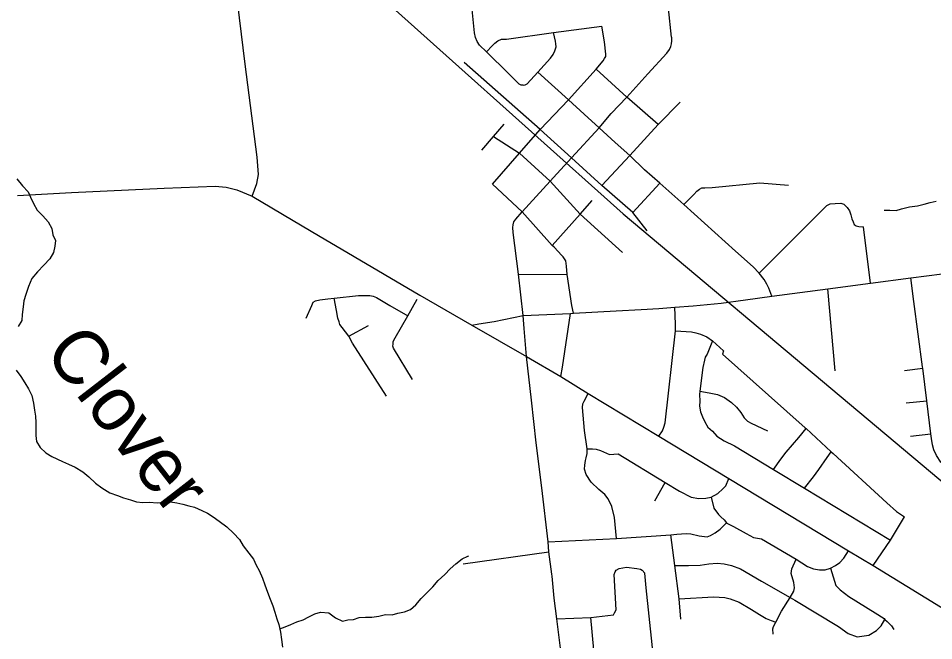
# Model space of a CAD drawing. Extents: x 114843 to 284848, y 317643 to 566895.
# Drawn here: x 156246 to 164672, y 408606 to 414334 of the extents above; entities that cross this region are included whole.
import ezdxf

# ---------------------------------------------------------------- set-up
doc = ezdxf.new("R2010")
doc.units = 0
for name, color, linetype in [('GM_X_City_Street', 7, 'Continuous'), ('GM_X_County_Road', 7, 'Continuous'), ('GM_X_Minor_River', 7, 'Continuous'), ('GM_X_Minor_River_Text', 7, 'Continuous'), ('GM_X_Rail_Line', 7, 'Continuous')]:
    doc.layers.add(name, color=color, linetype=linetype)

msp = doc.modelspace()

# ---------------------------------------------------------------- linework, layer by layer
at = {"layer": 'GM_X_City_Street'}
for p, q in [((161902.9, 412546.1), (162152.3, 412817.2)), ((164090.6, 411896.7), (164027.6, 412413.6)), ((160849.1, 411978.3), (161299.5, 411975.8)), ((163766.8, 411091.1), (163696.7, 411845.5)), ((159289.1, 411407.6), (159470.8, 411506)), ((164402.7, 411093.2), (164572.3, 411113.7)), ((164419.5, 410796.3), (164609.3, 410813.9)), ((164460.3, 410489.5), (164646.9, 410510)), ((162104.6, 409891.9), (162200.3, 410061)), ((160342.6, 409314.4), (161129.8, 409424))]:
    msp.add_line(p, q, dxfattribs=at)
for points in [[(160893, 413717.5), (160875.8, 413718.9), (160857.8, 413728.2), (160759.5, 413826.6), (160555.2, 414024.2), (160492.3, 414087.7), (160470.2, 414120.4), (160455.9, 414157.7), (160446.2, 414199.8), (160424.3, 414415.1)], [(160555.2, 414024.2), (160607.8, 414080.8), (160632.6, 414105.9), (160659, 414128), (160693.3, 414140.7), (160739.1, 414143.1), (161173.5, 414202.2), (161617.6, 414262.7)], [(160612, 412807.9), (160860.1, 413094.1), (161048.9, 413311.2), (161311.6, 413583.1), (161565.6, 413865.2), (161629.8, 413943.7), (161641.3, 413963.3), (161653.7, 413981.3), (161655.1, 414004.8), (161641.8, 414118.6), (161617.6, 414262.7)], [(160893, 413717.5), (160912.5, 413720.8), (160931.2, 413731.1), (161027.2, 413839.5), (161144.1, 413968.3), (161168.1, 414000.5), (161185.8, 414034.2), (161196.4, 414070.9), (161195.5, 414098.3), (161191.4, 414124.8), (161173.5, 414202.2)], [(162034, 412377.6), (161902.9, 412546.1), (161618.5, 412793.9), (161337.8, 413050.3), (161048.9, 413311.2), (160349.6, 413928.6)], [(161592.8, 413325.1), (161454.6, 413453), (161311.6, 413583.1), (161027.2, 413839.5)], [(162135.9, 413356.5), (161847.8, 413609.9), (161565.6, 413865.2)], [(161618.5, 412793.9), (161874.1, 413072), (162135.9, 413356.5), (162338.9, 413562.4)], [(160512.9, 413120.2), (160621.5, 413246.3), (160718.4, 413358.8)], [(163181.5, 411775.6), (163154.4, 411849.5), (163135.4, 411887.6), (163110.9, 411931.2), (163066, 411989.4), (163010.2, 412046), (162848.3, 412190), (162372.2, 412619), (162152.3, 412817.2), (162010.9, 412941.1), (161874.1, 413072), (161739.5, 413189.7), (161592.8, 413325.1)], [(160621.5, 413246.3), (160860.1, 413094.1), (161141.1, 412834.6), (161416.6, 412530.9), (161807, 412179.7)], [(161275.2, 412119.4), (161263, 412137.4), (161246.9, 412155.2), (161216.6, 412187), (161178.3, 412226.7), (161161.8, 412242.1), (160884.6, 412552.9), (160612, 412807.9)], [(162372.2, 412619), (162462.9, 412712.5), (162491.6, 412742.4), (162517.2, 412762.1), (162539, 412772.4), (162566.3, 412774.9), (162632.6, 412778.5), (163073.3, 412819.2), (163336.8, 412797.6)], [(161161.8, 412242.1), (161416.6, 412530.9), (161528, 412657.2)], [(163066, 411989.4), (163690.1, 412612.7), (163718, 412627), (163765.9, 412629.5), (163817.8, 412632), (163845.9, 412622.3), (163876.1, 412592.5), (163896.3, 412562.6), (163910.7, 412524.7), (163919, 412488.7), (163931.2, 412460.7), (163939.4, 412436.8), (163957.6, 412422.9), (163983.6, 412419.2), (164027.6, 412413.6)], [(161356.5, 411619), (161340.3, 411690), (161299.5, 411975.8), (161291.8, 412053.4), (161287.3, 412101.5), (161275.2, 412119.4)], [(165070.1, 409807.3), (165054, 409829.3), (165019.7, 409941.6), (165007.7, 409971.6), (164983.6, 410005.7), (164853.2, 410143.6), (164813.6, 410179.8), (164736.9, 410249.6), (164696.8, 410309.7), (164672.6, 410361.7), (164662.5, 410409.9), (164652.4, 410466), (164646.9, 410510), (164609.3, 410813.9), (164572.3, 411113.7), (164570.5, 411127.8), (164488.9, 411727.4), (164461.9, 411944.2)], [(158896.7, 411574.5), (158947.6, 411691.3), (158961.3, 411721.5), (158983.2, 411733.7), (159023.1, 411742.1), (159094.9, 411750.9), (159154.8, 411757.4), (159378.3, 411781.8), (159444.2, 411784.4), (159482.2, 411782.8), (159512.2, 411777.1), (159542.3, 411763.3), (159664.8, 411692.4), (159832.1, 411596.3)], [(159636.5, 410856.1), (159322.4, 411344.2), (159289.1, 411407.6), (159227.2, 411487.6), (159207, 411515.4), (159200.7, 411539.4), (159188.4, 411573.4), (159175.8, 411645.4), (159154.8, 411757.4)], [(159874.8, 411010.9), (159700.4, 411297.8), (159694.3, 411315.8), (159698.1, 411335.9), (159697.8, 411359.9), (159715.5, 411392.2), (159832.1, 411596.3), (159918.7, 411748.1)], [(162141.5, 410489.6), (162175.2, 410538.3), (162189.4, 410570.4), (162201.5, 410611.7), (162294.7, 411458), (162295.5, 411519.2), (162290.3, 411674.1)], [(161239.3, 411038), (161256.2, 411124.7), (161329.7, 411617.1)], [(162294.7, 411458), (162443.9, 411447.5), (162481.8, 411440.1), (162524.4, 411427.7), (162582.9, 411401.3), (162636.7, 411365), (162736.4, 411274.3), (162729.7, 411241.9), (163150.7, 410867.1), (163489.1, 410565.8), (163497.3, 410558.3), (163729.2, 410344.3), (163747, 410327.9), (164240, 409876.2), (164329.3, 409794.4), (164403.7, 409745.1)], [(162636.7, 411365), (162585.9, 411242.4), (162570.1, 411216.2), (162562.4, 411188.1), (162547, 411119.7), (162519.3, 410901.7), (162515.3, 410870.8), (162519.9, 410810.8), (162516.3, 410764.6), (162526.8, 410712.6), (162543.2, 410666.6), (162565.6, 410620.7), (162594, 410570.9), (162636.3, 410533.3), (162676.7, 410489.5), (162745, 410446.1), (162837.3, 410398.9), (163197.7, 410181.6), (163483.4, 410009.2), (164275.4, 409531.5)], [(161751.9, 409546), (161735.1, 409740.2), (161710.8, 409842.5), (161674.6, 409912.6), (161644.5, 409952.6), (161588.4, 409996.6), (161518.2, 410064.6), (161474, 410136.6), (161457.9, 410184.8), (161459.8, 410220.9), (161468.3, 410262.9), (161473.6, 410289.1), (161483.5, 410327.3), (161481.4, 410371.4), (161456.9, 410541.9), (161439.3, 410751.7), (161442.2, 410786.8), (161453.4, 410811.6), (161493.1, 410882)], [(162519.3, 410901.7), (162607.1, 410885.8), (162681.1, 410872.5), (162747.3, 410843.1), (162809.7, 410797.6), (162858, 410756), (162896.4, 410706.2), (162928.9, 410656.5), (162957.1, 410626.7), (162993.2, 410607), (163141.7, 410536.3)], [(163197.7, 410181.6), (163264, 410276.9), (163315.3, 410341.6), (163430, 410475), (163497.3, 410558.3)], [(161481.4, 410371.4), (161531.4, 410371.6), (161565.4, 410369.7), (161605.4, 410357.8), (161687.5, 410319.9), (161769.4, 410327.1), (162200.3, 410061), (162332.9, 409983.5), (162438.5, 409927.6), (162509.8, 409913.6), (162573.7, 409916.2), (162624.2, 409925.8), (162685.8, 409960.3), (162731.9, 410002.9), (162758.5, 410029.9), (162787.9, 410098.2)], [(163483.4, 410009.2), (163565.2, 410113.5), (163614.5, 410180.2), (163691.4, 410291.2), (163729.2, 410344.3)], [(162624.2, 409925.8), (162648.6, 409825.5), (162692.8, 409767.4), (162714.2, 409746), (162742.9, 409717.4), (162766, 409690.9), (162769, 409687.4), (162829, 409655.5), (162947.2, 409591.7), (163013.3, 409555.8), (163087.9, 409542.4), (163404.9, 409355.9), (163511.6, 409287.6), (163566.4, 409266.3), (163620.1, 409257.4), (163672.7, 409258.8), (163722.1, 409272.6), (163769.4, 409296.7), (163809.4, 409326.9), (163846.3, 409365.3), (163888, 409432.6)], [(161122.3, 409515.5), (161751.9, 409546), (162252.7, 409581.7), (162307.4, 409585.6), (162393.3, 409591.9), (162437.3, 409590.1), (162513.4, 409570.2), (162587.3, 409562.5), (162619.3, 409572.6), (162661.2, 409598.8), (162707.1, 409631.1), (162766, 409690.9)], [(164113.8, 409299.2), (164275.4, 409531.5), (164403.7, 409745.1)], [(162345.5, 408803.3), (162329.2, 408991.8), (162289.7, 409296.6), (162252.7, 409581.7)], [(163193.7, 408665.6), (163191.6, 408713.7), (163197.5, 408735.8), (163218.3, 408775.7), (163271.1, 408876.5), (163350.9, 409003.4), (163384.6, 409061.5), (163392.4, 409093.6), (163384.3, 409141.7), (163360.1, 409223.9), (163368, 409266.1), (163404.9, 409355.9)], [(161202.8, 408808.4), (161515.7, 408818.6), (161723.6, 408843.4), (161735.5, 408861.5), (161749.4, 408889.6), (161730.5, 409214.6), (161740.5, 409238.7), (161750.4, 409254.8), (161778.4, 409268.9), (161844.3, 409283.2), (161940.3, 409271.4), (161972.3, 409263.5), (161988.4, 409255.5)], [(162289.7, 409296.6), (162416.1, 409299.1), (162524.1, 409301.4), (162604, 409313.7), (162678, 409320), (162744, 409314.2), (162812, 409298.4), (162894.1, 409266.5), (163088.4, 409154.8), (163350.9, 409003.4), (163392.8, 408979.2), (163795.4, 408737.8), (163885.5, 408671.9), (163967.6, 408642.1), (164075.5, 408656.5), (164145.4, 408698.8), (164189.2, 408743.1), (164223.1, 408801.8)], [(163722.1, 409272.6), (163770.3, 409114.9), (163812.4, 409072.9), (163890.6, 409013), (164134.9, 408861.3), (164215.1, 408809.4), (164223.1, 408801.8), (164245.1, 408781.4), (164285.2, 408741.4), (164305.3, 408707.4)], [(162108.7, 408278.6), (162079.4, 408569.8), (162026.8, 409093.2), (162012.4, 409227.5), (161988.4, 409255.5)], [(162329.2, 408991.8), (162646.9, 409010.9), (162750.9, 409003.2), (162798.9, 408991.3), (162883, 408959.5), (162995.1, 408891.7), (163069.2, 408845.8), (163131.3, 408809.9), (163177.3, 408792), (163218.3, 408775.7)], [(161591.2, 408275.2), (161577.2, 408283.2), (161565.1, 408309.2), (161560.9, 408357.3), (161544.8, 408521.6), (161515.7, 408818.6)]]:
    msp.add_lwpolyline(points, dxfattribs=at)
at = {"layer": 'GM_X_County_Road'}
for p, q in [((158398.4, 412697.1), (158858.1, 412424.8)), ((160420.1, 411510.6), (160925.4, 411220.8)), ((160925.4, 411220.8), (161239.3, 411038))]:
    msp.add_line(p, q, dxfattribs=at)
for points in [[(158398.4, 412697.1), (158442, 412813.2), (158458.3, 412898.1), (158445.4, 413055.7), (158334.3, 413911.3), (158213.9, 414893.5), (158105, 415909.2), (158076.9, 416138.5)], [(162260.6, 414156.4), (162260.2, 414162), (162232.1, 414424.7), (162211.2, 414612.4), (162205.7, 414660.4)], [(161592.8, 413325.1), (161704.8, 413457.1), (161847.8, 413609.9), (162040, 413821.8), (162214.8, 414013.7), (162238.9, 414047.4), (162254, 414075), (162259.9, 414099.4), (162262.8, 414128.4), (162260.6, 414156.4)], [(161173.9, 412870.5), (161337.8, 413050.3), (161592.8, 413325.1)], [(160802.1, 412361.6), (160797.9, 412408.9), (160800, 412434.8), (160806.7, 412461.6), (160826.4, 412486.1), (160884.6, 412552.9), (161141.1, 412834.6), (161173.9, 412870.5)], [(156237.8, 412704.3), (156734.6, 412729.8), (157588.4, 412772), (158058.2, 412789.6), (158160.1, 412780.7), (158256.3, 412756.4), (158398.4, 412697.1)], [(163181.5, 411775.6), (163696.7, 411845.5), (164090.6, 411896.7), (164461.9, 411944.2), (164748.9, 411982.3), (165028, 412018.7), (165821.1, 412121.1), (166821.7, 412255.2), (168352.4, 412416.6), (169278.9, 412517.6), (169332.7, 412524.4)], [(158858.1, 412424.8), (159009.8, 412335), (159943.7, 411784.7), (160420.1, 411510.6)], [(160925.4, 411220.8), (160903.7, 411480.7), (160893.6, 411598.2), (160849.1, 411978.3), (160802.1, 412361.6)], [(161979.5, 411655.1), (162142.4, 411664.3), (162290.3, 411674.1), (162459.7, 411687.5), (162714.6, 411712), (162938.6, 411741.6), (163181.5, 411775.6)], [(160893.6, 411598.2), (161329.7, 411617.1), (161356.5, 411619), (161748.3, 411642.2), (161979.5, 411655.1)], [(160420.1, 411510.6), (160484.2, 411521.3), (160625.6, 411542.7), (160893.6, 411598.2)], [(161156.2, 409219), (161129.8, 409424), (161122.3, 409515.5), (161063.8, 410013.8), (161014.3, 410427.6), (160969.5, 410820), (160925.4, 411220.8)], [(161239.3, 411038), (161493.1, 410882), (162141.5, 410489.6), (162787.9, 410098.2), (163888, 409432.6), (164113.8, 409299.2), (164910.5, 408810.9), (165505.1, 408443.8), (166074.9, 408100.4), (166322.4, 407953.6), (166384.6, 407921.1), (166715.7, 407773.9), (166942.2, 407679.6), (167338.4, 407508.2), (167631.2, 407392.7), (167756, 407349.7)], [(161486.7, 407363.3), (161447.7, 407428.2), (161406.9, 407527.7), (161389.9, 407571.4), (161375.1, 407612.9), (161357.9, 407670.4), (161343.6, 407699), (161332.4, 407758.4), (161264.4, 408316.1), (161202.8, 408808.4), (161179.4, 408997.3), (161158.9, 409198.5), (161156.2, 409219)]]:
    msp.add_lwpolyline(points, dxfattribs=at)
at = {"layer": 'GM_X_Minor_River'}
for points in [[(156232.5, 412857.7), (156284.1, 412791.2), (156337.8, 412736.8), (156357.5, 412686.5)], [(156357.5, 412686.5), (156387.2, 412630.2), (156418.8, 412569.8), (156470.5, 412515.4), (156520.2, 412460.9), (156553.8, 412400.5), (156563.5, 412340.3), (156589.2, 412290), (156580.9, 412235.9), (156570.6, 412179.9), (156536.2, 412119.9), (156479.9, 412062.1), (156423.5, 412002.3), (156369.2, 411938.5), (156340.7, 411866.5), (156316.3, 411792.4), (156298, 411732.4), (156291.7, 411678.3), (156281.3, 411608.2), (156279, 411554), (156244.6, 411498.1)], [(164215.6, 412568.6), (164269.6, 412568.3), (164325.5, 412564), (164375.6, 412579.7), (164449.8, 412599.3), (164521.8, 412608.9), (164583.9, 412622.6), (164640, 412638.3), (164694.1, 412650)], [(156226.3, 411095.2), (156270, 411038.7), (156307.6, 410980.4), (156341.3, 410924), (156369, 410861.7), (156384.6, 410791.4), (156396.2, 410727.2), (156403.9, 410673), (156407.5, 410612.8), (156406.9, 410494.5), (156414.5, 410440.3), (156446.2, 410384), (156499.9, 410333.5), (156555.8, 410301.1), (156653.5, 410254.3), (156709.4, 410231.9), (156769.2, 410203.5), (156841, 410161), (156894.7, 410112.5), (156956.4, 410056), (157014.1, 410013.5), (157087.9, 409966.9), (157159.7, 409942.4), (157213.6, 409920), (157279.5, 409901.6), (157335.4, 409885.2), (157393.4, 409878.8), (157453.4, 409880.5), (157525.4, 409876), (157597.4, 409879.6), (157647.4, 409883.3), (157705.4, 409874.9), (157761.3, 409862.5), (157815.2, 409848.2), (157869.2, 409835.8), (157935, 409805.3), (157986.8, 409778.9), (158038.6, 409744.5), (158096.4, 409706.1), (158164.1, 409653.5), (158227.8, 409595), (158281.5, 409538.5), (158317.2, 409480.2), (158366.8, 409411.7), (158410.5, 409357.3), (158436.1, 409301), (158463.9, 409250.7), (158493.5, 409182.3), (158515.1, 409120), (158540.7, 409053.7), (158564.4, 408989.4), (158588, 408927.1), (158607.7, 408868.8), (158627.3, 408808.5), (158643, 408754.3), (158660.6, 408684), (158670.2, 408617.8), (158677.8, 408547.6)], [(158653, 408714.6), (158702.9, 408733.9), (158755, 408755.6), (158811.2, 408779.4), (158867.3, 408799.1), (158921.5, 408826.8), (158975.6, 408852.5), (159027.7, 408868.3), (159103.7, 408863.8), (159165.4, 408815.3), (159229.3, 408786.8), (159279.3, 408798.6), (159331.4, 408802.3), (159383.5, 408820), (159443.5, 408823.6), (159501.5, 408823.3), (159565.6, 408832.9), (159625.6, 408846.6), (159687.6, 408844.2), (159739.7, 408858), (159799.8, 408871.6), (159855.9, 408893.3), (159906.2, 408937.2), (159954.5, 408995), (160008.8, 409048.8), (160063.2, 409100.6), (160111.5, 409158.5), (160171.8, 409214.3), (160222.1, 409268.1), (160274.4, 409311.9), (160332.7, 409359.7), (160382.8, 409383.4), (160392.8, 409387.4)]]:
    msp.add_lwpolyline(points, dxfattribs=at)
at = {"layer": 'GM_X_Rail_Line'}
msp.add_lwpolyline([(147203, 425812.1), (147532.5, 425512.3), (151086.8, 422348.8), (154539.5, 419171.9), (158440.1, 415555.8), (161813.4, 412533.3), (168064.4, 407288.5)], dxfattribs=at)

# ---------------------------------------------------------------- texts
at = {"layer": 'GM_X_Minor_River_Text'}
msp.add_text('Clover', height=500.01, rotation=307.6809, dxfattribs=at).set_placement((156470.4, 411261.9))

doc.saveas('drawing.dxf')
